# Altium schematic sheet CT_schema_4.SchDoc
size 430 x 414 mm
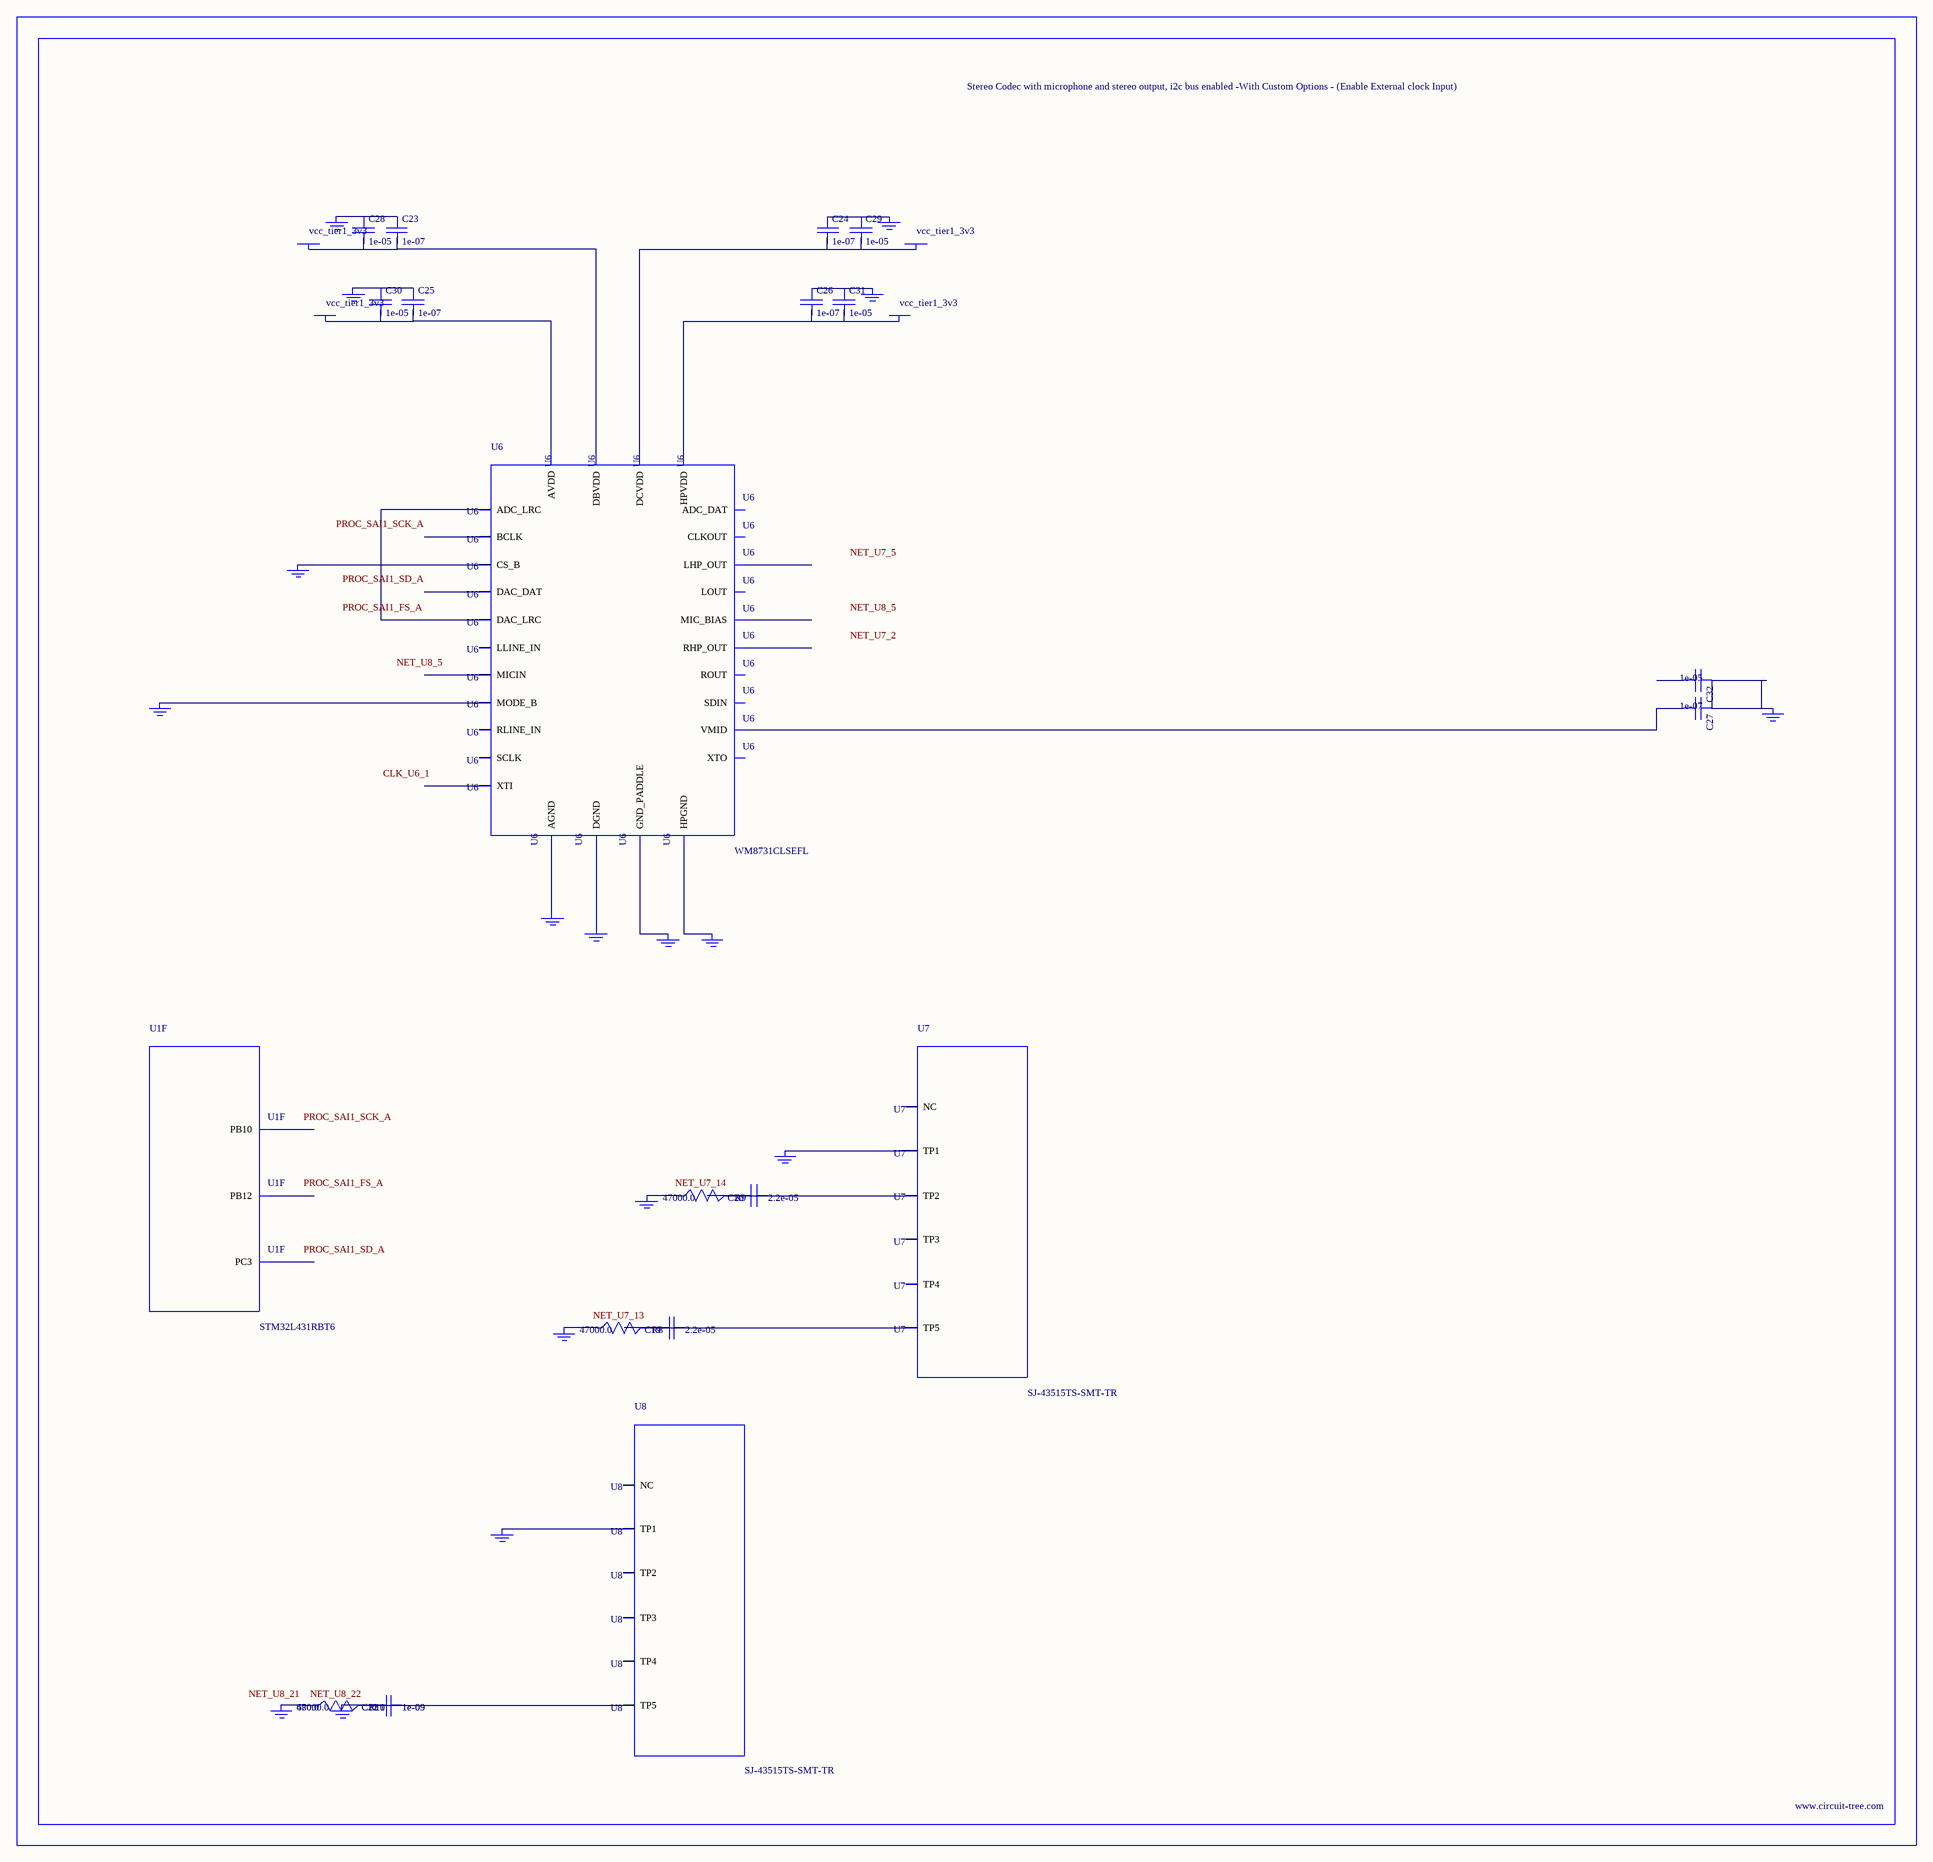
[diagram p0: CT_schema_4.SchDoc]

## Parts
BORDER3  (no value)
C19  2.2e-05  [C1210]
C20  2.2e-05  [C1210]
C21  1e-09  [C0402]
C22  1e-09  [C0402]
C23  1e-07  [C0402]
C24  1e-07  [C0402]
C25  1e-07  [C0402]
C26  1e-07  [C0402]
C27  1e-07  [C0402]
C28  1e-05  [C0805]
C29  1e-05  [C0805]
C30  1e-05  [C0805]
C31  1e-05  [C0805]
C32  1e-05  [C0805]
GND_INSTANCE_3_0  (no value)
GND_INSTANCE_3_1  (no value)
GND_INSTANCE_3_2  (no value)
GND_INSTANCE_3_3  (no value)
GND_INSTANCE_3_4  (no value)
GND_INSTANCE_3_5  (no value)
GND_INSTANCE_3_6  (no value)
GND_INSTANCE_3_7  (no value)
GND_INSTANCE_3_8  (no value)
GND_INSTANCE_3_9  (no value)
GND_INSTANCE_3_10  (no value)
GND_INSTANCE_3_11  (no value)
GND_INSTANCE_3_12  (no value)
GND_INSTANCE_3_13  (no value)
GND_INSTANCE_3_14  (no value)
GND_INSTANCE_3_15  (no value)
GND_INSTANCE_3_16  (no value)
POWER_INSTANCE_3_0  vcc_tier1_3v3
POWER_INSTANCE_3_1  vcc_tier1_3v3
POWER_INSTANCE_3_2  vcc_tier1_3v3
POWER_INSTANCE_3_3  vcc_tier1_3v3
R8  47000.0  [R0603]
R9  47000.0  [R0603]
R10  47000.0  [R0603]
R11  680.0  [R0603]
U1  STM32L431RBT6  [LQFP64]  (part F of 7)
U6  WM8731CLSEFL  [QFN-28]
U7  SJ-43515TS-SMT-TR  [SJ-43515TS-SMT-TR]
U8  SJ-43515TS-SMT-TR  [SJ-43515TS-SMT-TR]

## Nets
NetC19_1: C19.1 C19.2 R8.2 U7.5(TP5)
NetC20_1: C20.1 C20.2 R9.2 U7.2(TP2)
NetC21_1: C21.1 C21.2 C22.1 C22.2 GND_INSTANCE_3_16.0(GND) R10.2 R11.2 U8.5(TP5)
NetC23_1: C23.1 C28.1 GND_INSTANCE_3_1.0(GND)
NetC23_2: C23.2 C28.2 POWER_INSTANCE_3_1.0(PWR) U6.5(DBVDD)
NetC24_1: C24.1 C29.1 GND_INSTANCE_3_0.0(GND)
NetC24_2: C24.2 C29.2 POWER_INSTANCE_3_0.0(PWR) U6.3(DCVDD)
NetC25_1: C25.1 C30.1 GND_INSTANCE_3_4.0(GND)
NetC25_2: C25.2 C30.2 POWER_INSTANCE_3_3.0(PWR) U6.18(AVDD)
NetC26_1: C26.1 C31.1 GND_INSTANCE_3_2.0(GND)
NetC26_2: C26.2 C31.2 POWER_INSTANCE_3_2.0(PWR) U6.12(HPVDD)
NetC27_1: C27.1 C32.1 GND_INSTANCE_3_5.0(GND)
NetC27_2: C27.2 U6.20(VMID)
NetGND_INSTANCE_3_3_0: GND_INSTANCE_3_3.0(GND) U6.15(HPGND)
NetGND_INSTANCE_3_6_0: GND_INSTANCE_3_6.0(GND) U6.25(MODE_B)
NetGND_INSTANCE_3_7_0: GND_INSTANCE_3_7.0(GND) U6.26(CS_B)
NetGND_INSTANCE_3_8_0: GND_INSTANCE_3_8.0(GND) U6.29(GND_PADDLE)
NetGND_INSTANCE_3_9_0: GND_INSTANCE_3_9.0(GND) U6.4(DGND)
NetGND_INSTANCE_3_10_0: GND_INSTANCE_3_10.0(GND) U6.19(AGND)
NetGND_INSTANCE_3_11_0: GND_INSTANCE_3_11.0(GND) U7.1(TP1)
NetGND_INSTANCE_3_12_0: GND_INSTANCE_3_12.0(GND) R9.1
NetGND_INSTANCE_3_13_0: GND_INSTANCE_3_13.0(GND) R8.1
NetGND_INSTANCE_3_14_0: GND_INSTANCE_3_14.0(GND) U8.1(TP1)
NetGND_INSTANCE_3_15_0: GND_INSTANCE_3_15.0(GND) R10.1 R11.1
NetU6_9: U6.9(DAC_LRC) U6.11(ADC_LRC)

Not connected (* = marked no-connect by the designer): C32 2; U1 11(PC3) 29(PB10) 33(PB12); U6 1(XTI) 2(XTO) 6(CLKOUT) 7(BCLK) 8(DAC_DAT) 10(ADC_DAT) 13(LHP_OUT) 14(RHP_OUT) 16(LOUT) 17(ROUT) 21(MIC_BIAS) 22(MICIN) 23(RLINE_IN) 24(LLINE_IN) 27(SDIN) 28(SCLK); U7 3(TP3) 4(TP4) 6(NC); U8 2(TP2) 3(TP3) 4(TP4) 6(NC)

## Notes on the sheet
- Labels drawn without touching a wire or pin: CLK_U6_1, NET_U7_2, NET_U7_5, NET_U7_13, NET_U7_14, NET_U8_5, NET_U8_21, NET_U8_22, PROC_SAI1_FS_A, PROC_SAI1_SCK_A, PROC_SAI1_SD_A

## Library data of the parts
BORDER3 = BORDER_PAGE3
C19 C20 = C1210C224K5RACTU
C21 C22 = C0402C102K3RAC
C23-C27 = C0402C104K3RACTU
C28-C32 = C0805C106K8RACTU
GND_INSTANCE_3_0-GND_INSTANCE_3_16 = GND
POWER_INSTANCE_3_0-POWER_INSTANCE_3_3 = PWR
R8-R10 = RC0603JR-0747KL
R11 = RC0603JR-07680RL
